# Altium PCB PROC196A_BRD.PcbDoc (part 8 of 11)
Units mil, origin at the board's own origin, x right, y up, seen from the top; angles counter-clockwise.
Board outline 3346.45 x 4921.26 mil, 8 copper layers (Top Layer, GND1, SIG1, PWR1, PWR2, SIG2, GND2, Bottom Layer), stack 54.534 mil thick; 736 components, 498 nets, 3030 pads, 1279 vias.
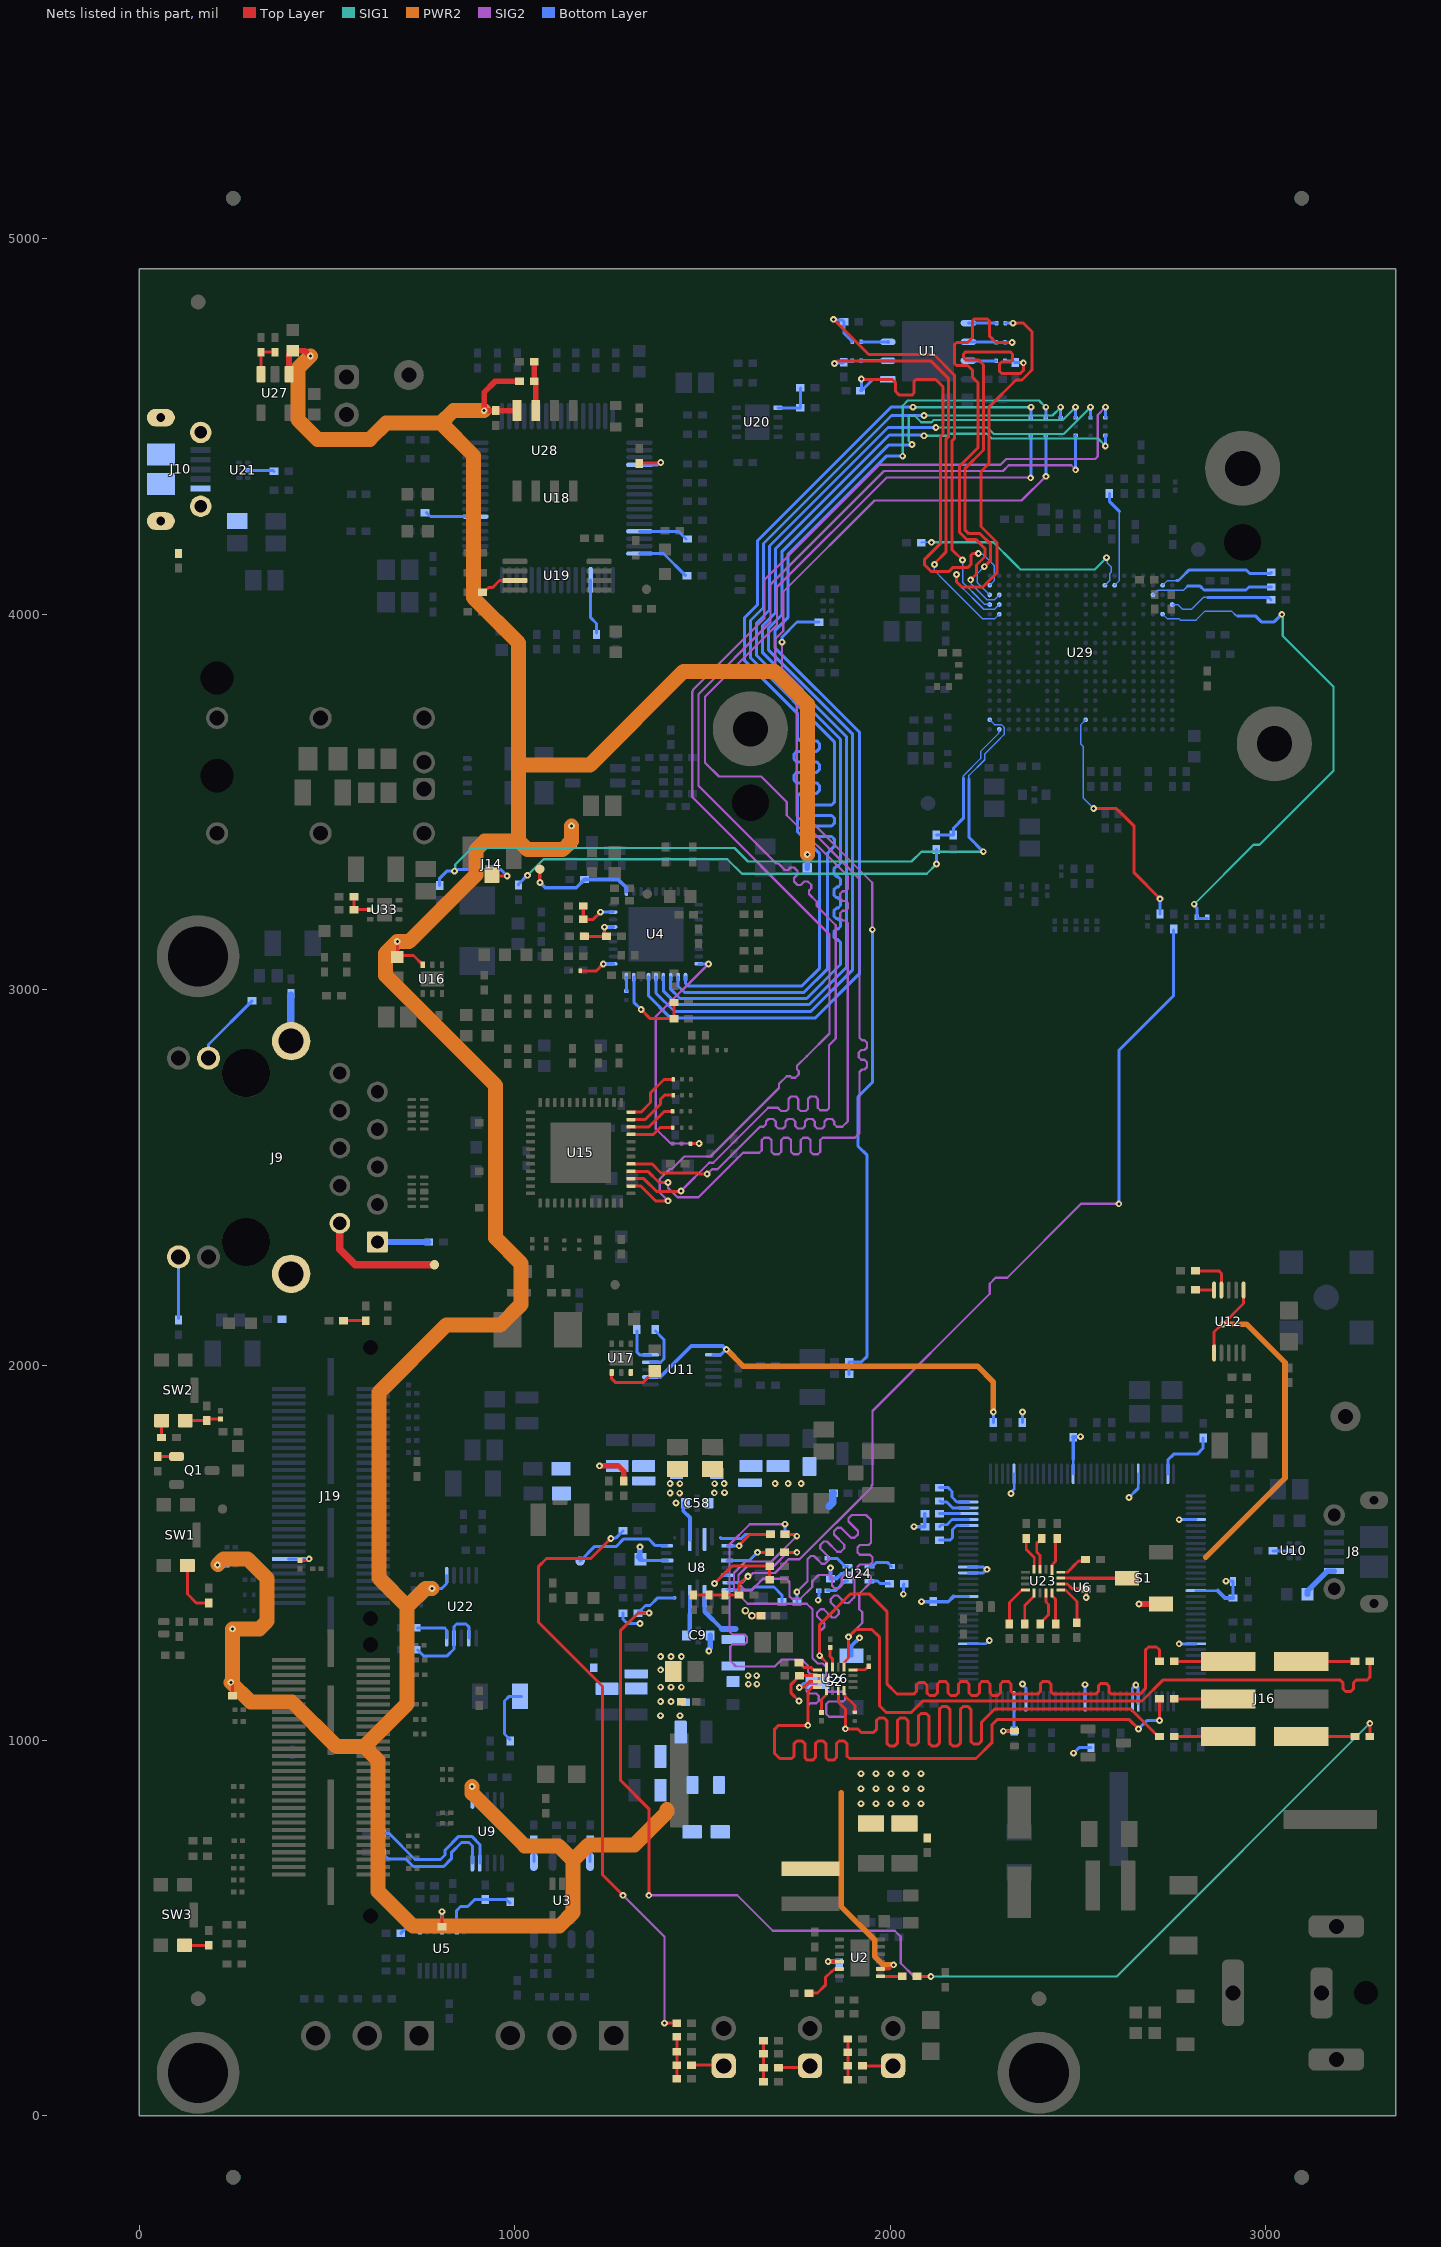
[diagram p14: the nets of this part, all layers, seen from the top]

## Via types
v1: diameter 18, hole 8, Top Layer to Bottom Layer, tented both sides, 1230 vias
v2: diameter 19.68, hole 7.87, Top Layer to Bottom Layer, 30 vias
v3: diameter 20, hole 10, Top Layer to Bottom Layer, tented both sides, 11 vias
v4: diameter 10, hole 4, SIG2 to Bottom Layer, tented both sides, 6 vias
v5: diameter 19.68, hole 7.87, Top Layer to Bottom Layer, tented both sides, 2 vias

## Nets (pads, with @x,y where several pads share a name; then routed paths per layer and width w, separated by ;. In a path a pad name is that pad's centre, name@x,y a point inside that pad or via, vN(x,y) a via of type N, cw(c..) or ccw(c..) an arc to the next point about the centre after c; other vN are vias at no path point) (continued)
NetJ8_5: J8.5 R175.2 | length 101.3
  Bottom Layer w15: R175.2@3112.06,1389.75 3112.06,1398.09 3165.02,1451.05 J8.5@3183.06,1451.05
NetJ9_1: J9.1 R400.1 | length 136.7
  Bottom Layer w15: J9.1@634.18,2327.93 R400.1@770.84,2327.93
NetJ9_2: J9.2 TP6.1 | length 338.4
  Top Layer w20: J9.2@534.18,2377.93 534.18,2308.46 575.32,2267.32 TP6.1@786.03,2267.32
NetJ9_11: J9.11 R69.1 | length 200.9
  Bottom Layer w8: J9.11@184.18,2817.7 184.18,2854.17 R69.1@300.41,2970.41
NetJ9_14: J9.14 R68.2 | length 164
  Bottom Layer w8: R68.2@104.25,2124.16 J9.14@104.25,2288.17
NetJ9_15: J9.15 R401.1
NetJ9_16: J9.16 R419.1 | length 122.8
  Bottom Layer w20: R419.1@403.86,2985.56 403.86,2863.36 J9.16@404.25,2862.97
NetJ10_1: J10.1 R206.1
NetJ10_6: J10.6 J10.7 J10.8 J10.9 J10.10 J10.11 R209.2
NetJ14_1: J14.1 R90.2 | length 95.6
  Top Layer w8: J14.1@939.4,3304.81 941.21,3303 v1(980,3303)
  Bottom Layer w8: R90.2@933.09,3320.81 962.19,3320.81 v1(980,3303)
NetJ16_1: J16.1 R5.2 | length 143.3
  Top Layer w8: R5.2@2757.14,1210.62 J16.1@2900.39,1210.62
NetJ16_2: J16.2 R61.1 | length 139.3
  Top Layer w8: J16.2@3095.27,1210.62 R61.1@3234.59,1210.62
NetJ16_3: J16.3 R167.2 | length 139.3
  Top Layer w8: R167.2@2761.07,1110.62 J16.3@2900.39,1110.62
NetJ16_5: J16.5 R176.2 | length 143.3
  Top Layer w8: R176.2@2757.14,1010.62 J16.5@2900.39,1010.62
NetJ17_1: J17.1 R300.2 | length 86.7
  Top Layer w8: R300.2@1471.02,135.11 1554.6,135.11 J17.1@1556.83,132.88
NetJ18_1: J18.1 R306.2 | length 84.4
  Top Layer w8: R306.2@1702.27,128.35 J18.1@1786.62,128.35
NetJ19_13: J19.13 R72.2 | length 89.4
  Top Layer w8: R72.2@427.98,1479.56 448.01,1479.56 v1(452.42,1483.98)
  Bottom Layer w8: J19.13@397.49,1483.81 456.43,1483.81 456.5,1483.88 452.52,1483.88 v1(452.42,1483.98)
NetJ20_1: J20.1 R311.2 | length 81.2
  Top Layer w8: R311.2@1926.71,133.08 J20.1@2007.9,133.08
NetL1_1: L1.1 U8.11 | length 142.1
  Bottom Layer w11: 1506,1342.9 U8.11@1506,1383.77
  Bottom Layer w12: 1506,1342.9 1552.01,1296.89
  Bottom Layer w15: 1552.01,1296.89 1588.19,1296.89
NetQ1_1: Q1.1 R266.2 | length 49.5
  Top Layer w8: R266.2@49.46,1756.63 Q1.1@99.01,1756.63
NetR1_1: R1.1 U2.5 | length 121.1
  Top Layer w8: R1.1@1783.91,326.87 1806.77,326.87 1827.57,347.67 1827.57,368.47 1842.33,383.23 ; 1843.25,384.15 1842.33,383.23 ; U2.5@1864.88,391.1 1852.05,391.1 1844.17,383.23 1842.33,383.23
NetR2_2: R2.2 U2.4 | length 56.9
  Top Layer w10: v1@1837.92,410.79 U2.4@1864.88,410.79
  Bottom Layer w10: v1(1834.92,410.78) R2.2@1855.07,410.78 ; R2.2@1855.08,410.79 R2.2@1864.88,410.79
NetR3_2: R3.2 U29.P20 | length 284.2
  Bottom Layer w4: U29.P20@2751.52,4026.2 2766.34,4026.2 2779.17,4013.37 2802.64,4013.37 2834.27,4045 2845.56,4045
  Bottom Layer w8: 2845.56,4045 3002.26,4045 3002.67,4044.59 3008.92,4044.59 R3.2@3014.76,4038.75
NetR4_2: R4.2 U2.7 | length 54
  Top Layer w8: U2.7@1974.33,371.42 R4.2@2028.34,371.42
NetR11_2: R11.2 U3.1 | length 58.1
  Bottom Layer w8: U3.1@1050.93,676.93 R11.2@1050.93,735.03
NetR12_2: R12.2 U3.4 | length 58.1
  Bottom Layer w8: U3.4@1200.93,676.93 R12.2@1200.93,735.03
NetR21_2: R21.2 U5.1 | length 58.1
  Bottom Layer w8: R21.2@696.51,486.19 714.23,503.91 U5.1@747.25,503.91
NetR25_2: R25.2 U5.4 | length 79.9
  Top Layer w8: R25.2@806.31,503.91 v1(806.31,543.87)
  Bottom Layer w8: U5.4@806.31,503.91 v1(806.31,543.87)
NetR27_1: R27.1 U9.5 | length 343.9
  Bottom Layer w8: R27.1@644.71,702.3 662.93,684.08 709.84,684.08 729.9,664.03 810.61,664.03 831.08,684.5 831.08,700.97 857.97,727.87 878.28,727.87 887.37,718.78 U9.5@887.37,673.26
NetR29_1: R29.1 U9.4 | length 382.7
  Bottom Layer w8: R29.1@644.71,752.49 664.91,752.49 734.59,682.81 802.15,682.81 814.2,694.86 814.2,707.57 851.1,744.47 885.41,744.47 907.05,722.82 U9.4@907.05,673.26
NetR31_2: R31.2 U29.T19 | length 312.1
  Bottom Layer w4: U29.T19@2725.93,4077.38 2738.65,4090.1 2746.2,4090.1 2746.24,4090.14 2756.81,4090.14 2756.84,4090.1 2763.44,4090.1
  Bottom Layer w8: 2763.44,4090.1 2768.33,4090.1 2777.67,4099.44 2797.04,4118.81 2925.19,4118.81 2948,4118.81 2958,4108.81 3012.48,4108.81 R31.2@3015.48,4111.81
NetR33_1: R33.1 U11.5 | length 95.3
  Bottom Layer w8: R33.1@1325.38,2090.69 1325.38,2052.36 1325.38,2034.89 1333.05,2027.22 U11.5@1361.7,2027.22
NetR35_1: R35.1 U11.4 | length 122.8
  Bottom Layer w8: U11.4@1361.7,2007.53 1388.65,2007.53 1390.85,2009.73 1397.04,2015.92 1397.04,2068.41 R35.1@1374.75,2090.69
NetR50_1: R50.1 R350.1 U4.8 | length 123
  Top Layer w8.3: R350.1@1182.57,3222.97 R50.1@1182.57,3187.4 1209.08,3187.4 v1(1228.3,3206.62)
  Bottom Layer w8: v1(1228.3,3206.62) U4.8@1262.03,3206.62
NetR53_2: R53.2 R54.2 U5.6 | length 201.8
  Bottom Layer w8: U5.6@845.68,503.91 845.21,504.38 845.21,547.17 855.58,557.53 874.69,557.53 893.01,575.85 R54.2@921.27,575.85 978.19,575.85 R53.2@987.76,566.27
NetR57_1: R57.1 U22.5 | length 101.5
  Bottom Layer w8: R57.1@741.42,1300.21 812.72,1300.21 818.5,1294.43 U22.5@818.5,1272.38
NetR58_1: R58.1 U12.5 | length 48.7
  Top Layer w8: R58.1@2813.85,2200.17 U12.5@2862.53,2200.17
NetR59_1: R59.1 U12.4 | length 116.4
  Top Layer w8: R59.1@2813.48,2251 2875.67,2251 2882.66,2244.01 U12.4@2882.66,2199.72
NetR62_1: R62.1 U22.2 U22.4 | length 245.8
  Bottom Layer w8: R62.1@741.42,1241.15 757.11,1225.47 819.92,1225.47 838.18,1243.72 U22.4@838.18,1272.38 838.18,1303.1 845.14,1310.06 870.2,1310.06 877.55,1302.71 U22.2@877.55,1272.38
NetR63_1: R63.1 U8.1 | length 137.8
  Bottom Layer w8: U8.1@1548.07,1539.66 1549.24,1538.49 1604.24,1538.49 1615,1549.25 R63.1@1680.91,1549.25
NetR74_2: R74.2 U4.28 | length 2871.7
  SIG1 w6: v1(2061.17,4551.81) v1(2375.05,4551.79)
  Bottom Layer w8: U4.28@1454.94,3033.39 1454.94,3016.44 1461.09,3010.3 1765.12,3010.3 1812.28,3057.46 1812.28,3362 1753.86,3420.42 1753.86,3497.5 1753.86,3516.21 1760.86,3523.21 1804.31,3523.21 1811.31,3530.21 1811.31,3544.21 1804.31,3551.21 1750.84,3551.21 1743.84,3558.21 1743.84,3572.21 1750.84,3579.21 1804.31,3579.21 1811.31,3586.21 1811.31,3600.21 1804.31,3607.21 1750.84,3607.21 1743.84,3614.21 1743.84,3628.21 1750.84,3635.21 1804.31,3635.21 1811.31,3642.21 1811.31,3656.21 1804.31,3663.21 1760.86,3663.21 1753.86,3670.21 1753.86,3674.21 1753.86,3735.09 1611.51,3877.44 1611.51,3990.39 1646.18,4025.06 1646.18,4195.41 2002.59,4551.81 2016.88,4551.81 v1(2061.17,4551.81) ; R74.2@2375.03,4523.93 v1(2375.05,4551.79)
NetR77_2: R77.2 R79.2 U4.35 | length 236.9
  Top Layer w8: v1@1338.51,2948.92 v1(1336.83,2947.25) 1361.27,2922.81 R79.2@1423.88,2922.81 R77.2@1423.88,2965.88
  Bottom Layer w8: U4.35@1317.15,3033.39 1317.15,2966.94 v1(1336.83,2947.25)
NetR89_1: R89.1 R93.2 U4.6 | length 109.4
  Top Layer w8: R89.1@1185.77,3142.2 R93.2@1244.83,3142.2 1244.75,3142.2 1238.91,3148.05 v1(1238.91,3166.67)
  Bottom Layer w10: v1(1238.91,3166.67) 1239.42,3167.17 1261.95,3167.17 U4.6@1262.03,3167.25
NetR96_2: R96.2 U4.33 | length 2881.4
  SIG1 w6: v1(2033.5,4421.31) 2033.5,4556.01 2047.3,4569.81 2396.73,4569.81 v1(2414.74,4551.79)
  Bottom Layer w8: U4.33@1356.52,3033.39 1356.52,2983.68 1415.92,2924.28 1799.64,2924.28 1919.1,3043.74 1919.1,3685.11 1693.01,3911.2 1693.01,3956.63 1727.68,3991.3 1727.68,4159.57 1989.42,4421.31 v1(2033.5,4421.31) ; R96.2@2414.73,4523.93 v1(2414.74,4551.79)
NetR100_2: R100.2 U4.32 | length 2894.6
  SIG1 w6: v1(2058.5,4452.31) 2058.5,4452.94 2049.62,4461.83 2049.62,4525.49 2053.13,4529 2065.85,4529 2083.04,4511.81 2110.2,4511.81 2116.2,4517.81 2460.15,4517.81 v1(2494.13,4551.79)
  Bottom Layer w8: U4.32@1376.2,3033.39 1376.2,2990.9 1425.44,2941.66 1788.69,2941.66 1900.43,3053.4 1900.43,3680.72 1676.71,3904.44 1676.71,3963.38 1711.38,3998.05 1711.38,4166.99 1995.16,4450.77 2058.5,4450.77 v1(2058.5,4452.31) ; R100.2@2494.11,4523.93 v1(2494.13,4551.79)
NetR110_2: R110.2 SW3.2 | length 64.7
  Top Layer w8: SW3.2@120.14,454.37 R110.2@184.83,454.37
NetR117_1: R117.1 R120.1 | length 59.1
  Top Layer w8: R120.1@544.29,2118.25 R117.1@603.35,2118.25
NetR123_1: R123.1 U6.63 | length 100.8
  Bottom Layer w8: R123.1@2131.95,1673.35 2155.02,1673.35 2164.91,1663.45 2164.91,1648.5 2177.9,1635.51 U6.63@2208.34,1635.51
NetR124_1: R124.1 U6.61 | length 53
  Bottom Layer w8: R124.1@2131.95,1604.01 U6.61@2184.93,1604.01
NetR126_1: R126.1 U6.62 | length 83.5
  Bottom Layer w7.8: R126.1@2132.49,1638.28 2135.62,1635.15 2150.89,1635.15 2166.29,1619.76 U6.62@2208.34,1619.76
NetR127_1: R127.1 U6.60 | length 84.2
  Bottom Layer w7.8: R127.1@2131.95,1569.43 2137.17,1574.65 2151.28,1574.65 2164.9,1588.26 U6.60@2208.34,1588.26
NetR152_2: R152.2 U6.95 | length 171.1
  Bottom Layer w7.87: U6.95@2739.83,1710.31 2739.83,1747.02 2755.55,1762.73 2818.25,1762.73 2833.89,1778.37 R152.2@2833.89,1805.76
NetR156_1: R156.1 R172.2 R316.2 | length 2244.2
  SIG2 w6: v1(1712,3925.81) 1712,3854.87 1768.29,3798.58 1768.29,3469.52 1952.62,3285.19 v1(1952.62,3160)
  Bottom Layer w8: v1(1712,3925.81) 1712.18,3925.99 1712.18,3939.33 1752.25,3979.4 R316.2@1810.99,3979.4 ; R172.2@1891.09,1975.11 R156.1@1891.09,2008.78 1923.78,2008.78 1938.87,2023.87 1938.87,2558.78 1914.53,2583.12 1914.53,2714.6 1952.62,2752.69 v1(1952.62,3160)
NetR158_1: R158.1 U18.48 | length 147.7
  Bottom Layer w8: U18.48@1332.18,4162.05 1396.17,4162.05 R158.1@1455.36,4102.86
NetR159_2: R159.2 R409.1 U27.3 | length 93.2
  Top Layer w8: U27.3@323.96,4642.54 R159.2@323.96,4698.33 R409.1@361.36,4698.33
NetR162_1: R162.1 U18.52 | length 147.5
  Bottom Layer w8: U18.52@1202.25,4091.18 1202.25,3991.22 1217.86,3975.62 R162.1@1217.86,3950.19
NetR174_2: R174.2 U10.5 | length 43.8
  Bottom Layer w8: R174.2@3020.18,1505.18 U10.5@3064.01,1505.18
NetR178_2: R178.2 U4.31 | length 2851.2
  SIG1 w6: v1(2090.28,4475.81) 2154.9,4475.81 2160.09,4481 2258.37,4481 2271.11,4468.25 2554.06,4468.25 v1(2573.48,4448.83)
  Bottom Layer w8: U4.31@1395.89,3033.39 1395.89,2997.2 1432.68,2960.41 1784.39,2960.41 1884.13,3060.16 1884.13,3673.97 1660.41,3897.69 1660.41,3970.13 1695.08,4004.8 1695.08,4175.15 1998.04,4478.11 2087.98,4478.11 v1(2090.28,4475.81) ; v1(2573.48,4448.83) R178.2@2573.5,4476.69
NetR179_1: R179.1 U18.36 | length 119.1
  Top Layer w8: R179.1@1332.18,4398.27 1337.42,4403.51 1387.7,4403.51 v1(1389,4404.81)
  Bottom Layer w8: U18.36@1332.18,4398.27 1379.83,4398.27 1386.38,4404.81 v1(1389,4404.81)
NetR186_1: R186.1 U8.8 | length 174.8
  Bottom Layer w8: U8.8@1566.83,1400.69 1631.52,1400.69 1639.36,1408.53 1690.56,1408.53 1712.22,1386.87 R186.1@1712.22,1369.65
NetR188_1: R188.1 U26.8 | length 46.2
  Top Layer w7.5: U26.8@1901.26,1188.16 1933.54,1188.16 R188.1@1943.39,1198
NetR190_2: R190.2 R292.2 U8.4 | length 155.4
  Top Layer w8: v1(1646.48,1501.05) R190.2@1679.37,1501.05
  Bottom Layer w8: U8.4@1565.85,1479.43 1624.86,1479.43 v1(1646.48,1501.05) R292.2@1679.37,1501.05
NetR193_1: R193.1 U8.2 | length 128.3
  Top Layer w8: v1(1597.94,1518.5) 1597.94,1520.82 1626.37,1549.25 R193.1@1680.91,1549.25
  Bottom Layer w8: U8.2@1566.83,1518.8 1566.98,1518.65 1597.79,1518.65 v1(1597.94,1518.5)
NetR194_2: R194.2 U6.59 | length 106
  Bottom Layer w5.5: U6.59@2184.07,1572.51 U6.59@2208.34,1572.51
  Bottom Layer w8: R194.2@2131.36,1533.4 2159.56,1533.4 2166.24,1540.09 2166.24,1561.98 2176.78,1572.51 U6.59@2184.07,1572.51
NetR202_1: R202.1 R203.1 U20.5 | length 108.7
  Bottom Layer w8: U20.5@1701.01,4550.19 R203.1@1756.72,4550.19 ; R203.1@1760.66,4550.19 R202.1@1760.66,4603.23
NetR205_2: R205.2 U19.3 | length 99.1
  Top Layer w8: R205.2@914.04,4059.35 917.98,4059.35 929.81,4071.18 940.65,4071.18 959.53,4090.06 U19.3@1000.42,4090.06
NetR208_2: R208.2 U21.5 | length 71
  Bottom Layer w8: U21.5@288.63,4383.75 355.97,4383.75 R208.2@358.57,4381.16
NetR222_1: R222.1 U24.3 | length 56
  Bottom Layer w8: U24.3@1945.05,1424.16 1966.79,1424.16 1967.26,1423.7 1967.79,1423.7 1972.92,1418.57 1996.78,1418.57 R222.1@1998.19,1417.16
NetR223_1: R223.1 U26.11 | length 54.1
  Top Layer w8: R223.1@1840.23,1247.66 1840.23,1223.83 1846.14,1217.92 U26.11@1846.14,1196.03
NetR225_2: R225.2 U4.30 | length 2880.9
  SIG1 w6: v1(2121.66,4497.81) 2258.53,4497.81 2276.08,4480.25 2462.28,4480.25 v1(2533.82,4551.79)
  Bottom Layer w8: U4.30@1415.57,3033.39 1415.57,3001.35 1440.21,2976.71 1777.63,2976.71 1867.83,3066.91 1867.83,3067.51 1867.83,3126.21 1860.83,3133.21 1857.08,3133.21 1850.08,3140.21 1850.08,3154.21 1857.08,3161.21 1860.83,3161.21 1867.83,3168.21 1867.83,3182.21 1860.83,3189.21 1857.08,3189.21 1850.08,3196.21 1850.08,3210.21 1857.08,3217.21 1860.83,3217.21 1867.83,3224.21 1867.83,3238.21 1860.83,3245.21 1857.08,3245.21 1850.08,3252.21 1850.08,3266.21 1857.08,3273.21 1860.83,3273.21 1867.83,3280.21 1867.83,3294.21 1860.83,3301.21 1857.08,3301.21 1850.08,3308.21 1850.08,3322.21 1857.08,3329.21 1860.83,3329.21 1867.83,3336.21 1867.83,3368.21 1867.83,3667.22 1644.11,3890.94 1644.11,3976.88 1678.78,4011.55 1678.78,4181.9 1994.69,4497.81 v1(2121.66,4497.81) ; R225.2@2533.81,4523.93 v1(2533.82,4551.79)
NetR230_2: R230.2 U4.29 | length 2927
  SIG1 w6: v1(2090.5,4529.81) 2432.45,4529.81 v1(2454.44,4551.79)
  Bottom Layer w8: U4.29@1435.26,3033.39 1435.26,3010.08 1452.33,2993.01 1770.88,2993.01 1833.78,3055.91 1833.78,3364.25 1851.53,3382 1851.53,3401.2 1844.53,3408.2 1796.13,3408.2 1789.13,3415.2 1789.13,3429.2 1796.13,3436.2 1844.53,3436.2 1851.53,3443.2 1851.53,3457.2 1844.53,3464.2 1777.16,3464.2 1770.16,3471.2 1770.16,3485.2 1777.16,3492.2 1844.53,3492.2 1851.53,3499.2 1851.53,3531.2 1851.53,3660.47 1627.81,3884.19 1627.81,3983.63 1662.48,4018.3 1662.48,4188.65 2003.64,4529.81 v1(2090.5,4529.81) ; R230.2@2454.42,4523.93 v1(2454.44,4551.79)
NetR234_2: R234.2 U4.27 | length 678.5
  Top Layer w8: R234.2@1468.15,2590.02 v1@1491.44,2590.02
  SIG2 w6: v1(1491.5,2590.08) 1415.73,2590.08 1376,2629.81 1376,2928.44 v1(1516.38,3068.82)
  Bottom Layer w8: U4.27@1490.38,3068.82 v1(1516.38,3068.82)
NetR247_2: R247.2 U4.36 | length 37.1
  Bottom Layer w8: R247.2@1297.46,2996.34 U4.36@1297.46,3033.39
NetR249_2: R249.2 U4.1 | length 95.1
  Top Layer w8: R249.2@1174.57,3050.42 1217.62,3050.42 v1(1236.03,3068.82)
  Bottom Layer w10: v1(1236.03,3068.82) U4.1@1262.03,3068.82
NetR250_1: R250.1 R314.2 U33.2 | length 77.7
  Top Layer w8: R250.1@571.34,3247.26 R314.2@571.34,3213.22 U33.2@615.03,3213.22
NetR251_2: R251.2 TP3.1 U4.10 | length 300.2
  Top Layer w10: TP3.1@1066.56,3321.29 1066.56,3286.29 v1(1066.99,3285.86)
  Bottom Layer w10: v1(1066.99,3285.86) 1081.18,3271.66 1163.72,3271.66 R251.2@1185.77,3293.72 1275.41,3293.72 1297.46,3271.66 U4.10@1297.46,3261.74
NetR267_2: R267.2 SW1.2 | length 143.3
  Top Layer w8: SW1.2@127.97,1466.29 127.97,1390.03 151.71,1366.29 R267.2@185.16,1366.29
NetR283_1: R283.1 U26.13 | length 57.1
  Top Layer w8: R283.1@1757.43,1206.86 1770.47,1193.82 1789.94,1193.82 1795.6,1188.16 U26.13@1806.77,1188.16
NetR296_1: R296.1 U23.13 | length 112.4
  Top Layer w7.5: U23.13@2454.79,1400.84 2454.98,1400.66 2467.37,1400.66 2497.52,1370.5 R296.1@2497.52,1313.41
NetR298_1: R298.1 R299.2 R300.1 R302.2 | length 111.8
  Top Layer w8: R298.1@1431.65,98.61 R300.1@1431.65,135.11 R302.2@1431.65,171.07 R299.2@1431.65,210.44
NetR304_1: R304.1 R305.2 R306.1 R307.2 | length 109.6
  Top Layer w8: R304.1@1662.9,90.41 R306.1@1662.9,128.35 R307.2@1662.9,165.74 R305.2@1662.9,199.99
NetR308_1: R308.1 R310.2 R311.1 R313.2 | length 108.6
  Top Layer w8: R308.1@1887.34,96.1 R311.1@1887.34,133.08 R313.2@1887.34,169.19 R310.2@1887.34,204.71
NetR317_2: R317.2 U24.4 | length 64.8
  Bottom Layer w8: R317.2@1832.34,1399.06 1854.4,1399.06 1879.5,1424.16 U24.4@1886.78,1424.16
NetR318_2: R318.2 U24.1 | length 67.9
  Bottom Layer w8: U24.1@1945.05,1463.53 1952.7,1463.53 1963.84,1474.67 1992.57,1474.67 R318.2@2003.7,1463.53
NetR319_1: R319.1 U24.6 | length 61
  Bottom Layer w8: R319.1@1834.75,1485.22 1858.58,1485.22 1880.26,1463.53 U24.6@1886.78,1463.53
NetR333_1: R333.1 SW2.4 | length 44.9
  Top Layer w8: R333.1@59.15,1807.13 SW2.4@59.15,1852.07
NetR334_1: R334.1 R335.2 SW2.2 | length 95.6
  Top Layer w8: SW2.2@122.14,1852.07 R335.2@179.39,1852.07 183.74,1856.42 R334.1@215.95,1856.42
NetR353_2: R353.2 U23.16 | length 80.1
  Top Layer w7.5: U23.16@2454.79,1448.09 2472.15,1448.09 2486.55,1462.49
  Top Layer w8: 2486.55,1462.49 2502.09,1478.04 2516.94,1478.04 R353.2@2520.83,1481.93
NetR354_2: R354.2 U23.1 | length 84.4
  Top Layer w7.5: U23.1@2431.17,1453.99 2431.17,1467.77 2440.88,1477.49 R354.2@2440.88,1534.37
NetR355_2: R355.2 U23.3 | length 85.8
  Top Layer w7.5: U23.3@2399.67,1455.96 2399.67,1493.14 2390.76,1502.05 2390.76,1525.46 R355.2@2399.67,1534.37
NetR356_2: R356.2 U23.4 | length 91.1
  Top Layer w7.5: R356.2@2362.88,1538.3 2362.88,1508.43 2383.92,1487.39 U23.4@2383.92,1455.96
NetR357_2: R357.2 U23.9 | length 92.7
  Top Layer w7.5: R357.2@2358.88,1310.63 2358.88,1359.73 2383.92,1384.78 U23.9@2383.92,1392.97
NetR358_2: R358.2 U23.8 | length 112.9
  Top Layer w7.5: R358.2@2317.88,1310.63 2317.88,1367.17 2351.56,1400.84 U23.8@2360.3,1400.84
NetR359_2: R359.2 U23.12 | length 82.4
  Top Layer w7.5: U23.12@2431.17,1392.97 2431.17,1385.74 2440.88,1376.02 R359.2@2440.88,1314.57
NetR360_2: R360.2 U23.11 | length 94.2
  Top Layer w7.5: R360.2@2399.67,1310.63 2405.76,1316.72 2405.76,1318.69 2421.83,1334.76 2421.83,1362.19 2415.42,1368.6 U23.11@2415.42,1392.97
NetR377_2: R377.2 U26.4 | length 69.4
  Top Layer w7.5: U26.4@1877.64,1133.04 1877.64,1121.23 1906.18,1092.68 R377.2@1906.18,1075.51
NetR380_2: R380.2 U29.T14 | length 260.8
  Bottom Layer w4: U29.T14@2597.98,4077.38 2610.81,4090.21 2610.81,4274.54
  Bottom Layer w8: R380.2@2583.89,4321.73 2583.89,4301.46 2610.81,4274.54
NetR381_2: R381.2 U29.T13 | length 623.1
  SIG1 w6: v1(2110,4191.81) 2275,4191.81 2328.74,4138.07 2339.11,4127.7 2347,4119.81 2545.64,4119.81 2553.53,4127.7 2563.9,4138.07 v1(2576.83,4151)
  Bottom Layer w4: R381.2@2083,4190.81 2084,4191.81 v1(2110,4191.81) ; U29.T13@2572.39,4077.38 2585.15,4090.14 2585.15,4108.81 2589.68,4113.34 2589.68,4125.89 2587.87,4127.7 2578.21,4137.36 2578.21,4138.07 2578.21,4149.62 v1(2576.83,4151)
NetR386_2: R386.2 U29.B11 | length 645.5
  Top Layer w8: v1(2542.38,3483) 2602.77,3483 2625,3460.77 2650.13,3435.64 2650.13,3311.33 v1(2719.16,3242.3)
  Bottom Layer w4: U29.B11@2521.21,3719.11 2508.38,3706.29 2508.38,3661.87 2508.38,3658.75 2508.38,3654.02 2514.34,3648.06 2514.34,3511.04 v1(2542.38,3483)
  Bottom Layer w8: R386.2@2719.16,3201.57 v1(2719.16,3242.3)
NetR392_2: R392.2 U29.R18 | length 332.2
  Bottom Layer w4: U29.R18@2700.34,4051.79 2713.21,4064.66 2777.67,4064.66 2782.42,4064.66 2792.76,4075
  Bottom Layer w8: 2792.76,4075 2826.06,4075 2836.06,4065 2925.19,4065 2948.38,4065 2956.19,4072.81 R392.2@3015.58,4072.81
NetR399_1: R399.1 U26.1 | length 63.9
  Top Layer w7.5: R399.1@1817.43,1076.52 1817.43,1109.23 1830.39,1122.2 U26.1@1830.39,1135.01
NetR416_1: R416.1 R417.2 U28.7 | length 131.2
  Top Layer w15: R417.2@1051.89,4672.69 R416.1@1051.89,4620.96 1055.83,4617.02 U28.7@1055.83,4543.13
NetS1_2: S1.2 U23.15 | length 176.2
  Top Layer w8: U23.15@2454.79,1432.34 2484,1432.34
  Top Layer w10: 2484,1432.34 S1.2@2631.01,1432.34
NetS2_2: S2.2 U26.15 | length 110.6
  Top Layer w8.3: v1(1757.99,1140.91) 1759.85,1142.77 1770.82,1142.77 1784.72,1156.66 U26.15@1806.77,1156.66
  Bottom Layer w8: v1(1757.99,1140.91) 1768.9,1151.82 1801.93,1151.82 S2.2@1806.77,1156.66
NetTP8_1: TP8.1 U8.22 | length 263.1
  Bottom Layer w8: TP8.1@1174.27,1478.02 1213.48,1517.23 1270.88,1517.23 1290.67,1537.03 1356.39,1537.03 1374.61,1518.8 U8.22@1405.42,1518.8
NRST_FTDI: R166.1 U18.45 | length 132.8
  Bottom Layer w8: U18.45@1332.18,4221.1 1435.99,4221.1 R166.1@1456.49,4200.6
NRSTOUT: R99.2 R102.1 U8.6 | length 245.1
  Top Layer w8: v5(1532.2,1418.01) 1578.46,1464.28 R102.1@1679.37,1464.28 R99.2@1679.37,1428.39
  Bottom Layer w8: v5(1532.2,1418.01) 1542.89,1428.7 1542.89,1428.91 1554.04,1440.06 U8.6@1565.85,1440.06
OSC_CLK_OUT_ETH: R88.1 R259.1 | length 1208.3
  SIG1 w6: v1(1033.7,3304.81) 1076.7,3347.81 1566.2,3347.81 1605.2,3308.81 2078,3308.81 2097.44,3308.81 v1(2123.44,3334.81)
  Bottom Layer w8: R259.1@1010.04,3279.18 1010.04,3281.15 v1(1033.7,3304.81) ; R88.1@2123.18,3373.13 2123.18,3335.07 v1(2123.44,3334.81)
OSC_CLK_OUT_ETHERNET: R88.2 R95.2 U29.A2 | length 377.5
  Bottom Layer w4: 2194.95,3564.28 2194.95,3569.66 2240.9,3615.61 2240.9,3634.93 2290.1,3684.13 2290.1,3692.73 U29.A2@2290.89,3693.52
  Bottom Layer w8: R88.2@2123.18,3412.5 R95.2@2167.78,3412.5 2169.33,3412.5 2169.33,3430.96 2194.95,3456.58 2194.95,3564.28
OSC_CLKTOP: R90.1 R367.1 U29.B1 | length 2025.7
  SIG1 w6: v1(839.69,3315.81) 841.38,3317.5 841.38,3333.81 885.38,3377.81 1585.41,3377.81 1621.7,3341.51 2057.17,3341.51 2083.47,3367.81 v1(2248.33,3367.81)
  Bottom Layer w4: 2210,3561.58 2210,3570.81 2252.05,3612.86 2252.05,3627.84 2282.96,3658.75 2286.08,3661.87 2303.76,3679.55 2303.76,3699.13 2296.5,3706.39 2278.02,3706.39 U29.B1@2265.3,3719.11
  Bottom Layer w8: R367.1@800.05,3277.5 800.05,3297.11 818.69,3315.75 839.63,3315.75 v1(839.69,3315.81) 842.4,3315.81 847.4,3320.81 R90.1@893.72,3320.81 ; 2210,3561.58 2210,3406.14 v1(2248.33,3367.81)
PMIC_CLK: R75.1 R297.2 | length 1653.2
  Top Layer w8: v1(1256.04,1537.99) 1202.6,1484.55 1084.7,1484.55 1062.74,1462.6 1062.74,1315.42 1234.43,1143.73 1234.43,641.79 v1(1288.68,587.54) ; v1(1398.87,246.66) R297.2@1431.65,246.66
  SIG2 w6: v1(1288.68,587.54) 1398.87,477.35 v1(1398.87,246.66)
  Bottom Layer w8: v1(1256.04,1537.99) 1256.98,1538.94 1269.11,1538.94 R75.1@1288.39,1558.22
PMIC_CLK_OUT: R218.1 R220.1 U29.N19 | length 1414.8
  SIG1 w6: v1(2810.27,3228) 2968.42,3386.15 2984.07,3386.15 3181.25,3583.33 3181.25,3806.96 3045.76,3942.45 3045.76,3997.81 v1(3043.47,4000.1)
  Bottom Layer w4: U29.N19@2725.93,4000.61 2738.8,3987.74 2770.59,3987.74 2773.65,3984.68 2815.17,3984.68 2839.07,4008.58 2909.51,4008.58 2922.09,3996 2925.19,3996
  Bottom Layer w8: v1(2810.27,3228) 2810.27,3224.75 2817.15,3217.87 2817.15,3190.15 R220.1@2845,3190.15 ; 2925.19,3996 2973.12,3996 2989.12,3980 3023.36,3980 v1(3043.47,4000.1)
PMIC_EN: R4.1 R125.1 R185.2 U8.15 | length 3376.4
  Top Layer w8: v1(1357.25,587.54) 1357.25,818.34 1281.2,894.39 1281.2,1292.13 1328.28,1339.21 v1(1358.31,1339.21) ; R4.1@2075.59,371.42 v1@2107.41,371.42 ; R185.2@3277.9,1010.62 v1(3277.9,1045.76)
  SIG1 w6: v1@2107.41,371.42 v1(2108.41,371.42) 2603.56,371.42 v1(3277.9,1045.76)
  SIG2 w6: v1(1357.25,587.54) 1592.5,587.54 1687.04,493 2012.67,493 2028.66,477.01 2028.66,406.52 2063.76,371.42 v1(2108.41,371.42)
  Bottom Layer w8: v1(1358.31,1339.21) R125.1@1328.05,1339.21 1348.41,1359.56 1360.65,1359.56 1380.92,1379.84 U8.15@1425.9,1379.84
PMIC_NINT: R13.2 R17.2 R106.1 R210.1 R214.2 U8.7 | length 2565.7
  Top Layer w8: R210.1@1475.62,1387.47 R13.2@1517.62,1387.47 R17.2@1560.12,1387.47 R106.1@1597.79,1387.47 1597.79,1416.02 1618.77,1437 v5(1621.35,1437)
  SIG2 w6: v5(1621.35,1437) 1625.05,1437 1634.44,1446.39 1693.45,1446.39 1729.45,1482.39 1758.43,1482.39 1950.19,1674.15 1950.19,1679.21 1952.84,1681.86 1952.84,1877.76 2265.37,2190.29 2265.37,2216.9 2281.01,2232.54 2311.85,2232.54 2508.81,2429.49 v1(2609.22,2429.49)
  Bottom Layer w8: U8.7@1568.31,1420.38 1604.75,1420.4 v5(1621.35,1437) ; v1(2609.22,2429.49) 2609.22,2838.18 2755.57,2984.53 R214.2@2755.57,3159.44
PMIC_SPI_CLK: R63.2 R167.1 U26.16 | length 2766.4
  Top Layer w8: U26.16@1806.77,1140.91 1790.92,1140.91 1780.68,1130.67 v1(1780.68,1040.29) 1702.85,1040.29 1692.65,1030.09 1692.65,965.32 1697.99,959.98 1706.15,951.81 1737.65,951.81 1744.65,958.81 1744.65,991.42 1751.65,998.42 1765.65,998.42 1772.65,991.42 1772.65,954.28 1779.65,947.28 1793.65,947.28 1800.65,954.28 1800.65,991.42 1807.65,998.42 1821.65,998.42 1828.65,991.42 1828.65,954.28 1835.65,947.28 1849.65,947.28 1856.65,954.28 1856.65,991.42 1863.65,998.42 1877.65,998.42 1884.65,991.42 1884.65,958.81 1891.65,951.81 1923.65,951.81 2229,951.81 2271.04,993.85 2271.04,1041.38 2285.09,1055.42 2637.39,1055.42 v1(2662,1030.81) ; R167.1@2717.77,1110.62 2717.77,1053.04 v1(2718,1052.81)
  SIG2 w6: v1(1719.85,1576.1) 1626.29,1576.1 1571.93,1521.74 1571.93,1290.58 1574.03,1288.48 1580.53,1281.98 1612.08,1281.98 1618.58,1275.48 1618.58,1262.48 1612.08,1255.98 1580.53,1255.98 1574.03,1249.48 1574.03,1220.48 1574.03,1212.55 1589.77,1196.81 1693,1196.81 1711.84,1215.65 1764.14,1215.65 1780.98,1198.81 1780.98,1190.56 1780.98,1183.26 1787.48,1176.76 1803.61,1176.76 1810.11,1170.26 1810.11,1157.26 1803.61,1150.76 1784.07,1150.76 1777.57,1144.26 1777.57,1131.26 1784.07,1124.76 1803.61,1124.76 1810.11,1118.26 1810.11,1105.26 1803.61,1098.76 1787.48,1098.76 1780.98,1092.26 1780.98,1063.26 1780.98,1040.59 v1(1780.68,1040.29)
  Bottom Layer w8: v1(1719.85,1576.1) 1719.85,1549.68 R63.2@1720.28,1549.25 ; v1(2662,1030.81) 2684,1052.81 v1(2718,1052.81)
PMIC_SPI_CS0: R5.1 R190.1 U26.12 | length 2888.4
  Top Layer w8: R190.1@1718.74,1501.05 v1(1751.63,1501.05) ; U26.12@1830.39,1196.03 1830.39,1207.84 v1(1812.35,1225.88) 1812.35,1308.16 1894.67,1390.48 1944.65,1390.48 1992.33,1342.8 1992.33,1149.99 2018.32,1124 2038.37,1124 2038.95,1123.42 2059,1123.42 2063,1123.42 2070,1130.42 2070,1147.46 2077,1154.46 2091,1154.46 2098,1147.46 2098,1126.79 2105,1119.79 2119,1119.79 2126,1126.79 2126,1150.65 2133,1157.65 2147,1157.65 2154,1150.65 2154,1126.79 2161,1119.79 2175,1119.79 2182,1126.79 2182,1150.65 2189,1157.65 2203,1157.65 2210,1150.65 2210,1126.79 2217,1119.79 2231,1119.79 2238,1126.79 2238,1150.65 2245,1157.65 2259,1157.65 2266,1150.65 2266,1126.79 2273,1119.79 2287,1119.79 2294,1126.79 2294,1150.65 2301,1157.65 2315,1157.65 2322,1150.65 2322,1130.42 2329,1123.42 2337.97,1123.42 2389.31,1123.42 2393.31,1123.42 2400.31,1130.42 2400.31,1150.65 2407.31,1157.65 2421.31,1157.65 2428.31,1150.65 2428.31,1130.42 2435.31,1123.42 2447,1123.42 2543.61,1123.42 2547.61,1123.42 2554.61,1130.42 2554.61,1145.17 2561.61,1152.17 2575.61,1152.17 2582.61,1145.17 2582.61,1130.42 2589.61,1123.42 2607.54,1123.42 2665.61,1123.42 2680,1137.81 2680,1240.46 2688.64,1249.09 2710,1249.09 2717.77,1241.33 R5.1@2717.77,1210.62
  SIG2 w6: v1(1751.63,1501.05) 1726.95,1501.05 1690.7,1464.79 1619.92,1464.79 1595.93,1440.8 1595.93,1418.09 1613.73,1400.29 1630.87,1400.29 1661.55,1430.96 1723.03,1430.96 1732.05,1421.95 1732.05,1383.77 1738.5,1377.31 1760.5,1377.31 1792.27,1409.08 1792.27,1424.08 1809.05,1440.86 1827.2,1440.86 1838.48,1440.86 1844.98,1434.36 1844.98,1412.82 1851.48,1406.32 1864.48,1406.32 1870.98,1412.82 1870.98,1434.36 1877.48,1440.86 1880.48,1440.86 1892.95,1440.86 1904.94,1428.87 1904.94,1381.91 1898.04,1375.01 1889.28,1366.25 1880.08,1366.25 1860.3,1386.04 1851.1,1386.04 1841.91,1376.85 1841.91,1367.66 1863.4,1346.16 1863.4,1336.97 1854.21,1327.78 1845.02,1327.78 1823.53,1349.27 1814.33,1349.27 1805.14,1340.08 1805.14,1330.89 1824.93,1311.1 1824.93,1301.9 1822.81,1299.78 1812.35,1289.32 v1(1812.35,1225.88)
PMIC_SPI_MISO: R176.1 R193.2 U26.3 | length 2795.1
  Top Layer w8: R193.2@1720.28,1549.25 1746.63,1549.25 v1(1751.63,1544.25) ; U26.3@1861.89,1133.04 1861.89,1102.54 1880.79,1083.64 v1(1880.79,1031) 1913.23,1031 1922.43,1021.8 1952.16,1021.8 1956.16,1021.8 1963.16,1028.8 1963.16,1052.55 1970.16,1059.55 1984.16,1059.55 1991.16,1052.55 1991.16,992.57 1998.16,985.57 2012.16,985.57 2019.16,992.57 2019.16,1052.55 2026.16,1059.55 2040.16,1059.55 2047.16,1052.55 2047.16,994.81 2054.16,987.81 2068.16,987.81 2075.16,994.81 2075.16,1064.91 2082.16,1071.91 2096.16,1071.91 2103.16,1064.91 2103.16,992.57 2110.16,985.57 2124.16,985.57 2131.16,992.57 2131.16,1082.79 2138.16,1089.79 2152.16,1089.79 2159.16,1082.79 2159.16,992.57 2166.16,985.57 2180.16,985.57 2187.16,992.57 2187.16,1082.79 2194.16,1089.79 2208.16,1089.79 2215.16,1082.79 2215.16,997.66 2222.16,990.66 2236.16,990.66 2243.16,997.66 2243.16,1048.01 2251,1055.85 2278.75,1083.59 2641.36,1083.59 2708.5,1016.46 2711.92,1016.46 R176.1@2717.77,1010.62
  SIG2 w6: v1(1751.63,1544.25) 1684.17,1476.79 1614.94,1476.79 1583.93,1445.78 1583.93,1400.74 1620.44,1364.23 1777.96,1364.23 1792.98,1349.21 1792.98,1219.22 1807.39,1204.81 1820.44,1204.81 1830,1195.25 1830,1152.56 1830,1136 1836.5,1129.5 1874.11,1129.5 1880.61,1123 1880.61,1110 1874.11,1103.5 1836.5,1103.5 1830,1097 1830,1070.81 1832.81,1068 1838,1062.81 1877.28,1062.81 1880.79,1059.3 v1(1880.79,1031)
PMIC_SPI_MOSI: R61.2 R186.2 U26.9 | length 2860.4
  Top Layer w8: U26.9@1877.64,1196.03 1877.7,1196.09 1877.7,1207.91 1889.27,1219.48 v1(1889.27,1276.15) 1908.19,1295.07 1952.09,1295.07 1971.13,1276.02 1971.13,1092.91 1989.49,1074.55 2056.59,1074.55 2086.83,1104.79 2670.9,1104.79 2726.61,1160.51 3167.31,1160.51 3199.31,1160.51 3206.31,1153.51 3206.31,1137.46 3213.31,1130.46 3227.31,1130.46 3234.31,1137.46 3234.31,1153.51 3241.31,1160.51 3270.26,1160.51 3274.79,1165.04 3277.9,1168.15 R61.2@3277.9,1210.62
  SIG2 w6: v1(1751.63,1395.6) 1779.96,1423.93 1779.96,1467.65 1779.96,1482.77 1788.31,1491.12 1797.5,1491.12 1817.62,1471.01 1826.81,1471.01 1836,1480.2 1836,1489.39 1813.8,1511.6 1813.8,1520.79 1822.99,1529.98 1832.18,1529.98 1859.2,1502.96 1868.4,1502.96 1877.59,1512.15 1877.59,1521.34 1850.56,1548.37 1850.56,1557.56 1859.76,1566.75 1868.95,1566.75 1895.97,1539.73 1905.17,1539.73 1914.36,1548.92 1914.36,1558.11 1889.43,1583.04 1889.43,1592.24 1898,1600.81 1922.77,1600.81 1936,1600.81 1949,1587.81 1949,1555.98 1949,1526.97 1942.5,1520.47 1919.42,1520.47 1912.92,1513.97 1912.92,1500.97 1919.42,1494.47 1946.69,1494.47 1953.19,1487.97 1953.19,1474.97 1946.69,1468.47 1919.42,1468.47 1912.92,1461.97 1912.92,1448.97 1919.42,1442.47 1942.5,1442.47 1949,1435.97 1949,1432.96 1949,1421.81 1918,1390.81 1918,1349.81 1925.9,1341.91 1925.9,1312.78 v1(1889.27,1276.15)
  Bottom Layer w8: R186.2@1751.59,1369.65 v1(1751.63,1395.6) v1(1751.63,1395.6)
PMIC_WAKE: J16.6 R185.1 | length 143.3
  Top Layer w8: J16.6@3095.27,1010.62 3190.9,1010.62 R185.1@3238.53,1010.62
PMICOUT_1V0: C132.1 C134.1 L8.2 R71.2 R73.1 R111.1 | length 96.5
  Top Layer w15: v1(1225.73,1731.54) 1276.05,1731.54 1290.05,1717.54 R71.2@1290.05,1691.14
PMICOUT_1V2: C129.1 C130.1 L2.2 R30.1 R32.1 R291.2 | length 159.5
  Bottom Layer w8: R32.1@987.91,1002.01 972.72,1017.2 972.72,1105.08 985.26,1117.62 R30.1@1013.71,1117.62 R30.1@1017.64,1117.62
PMICOUT_1V8: C60.1 C125.1 C127.1 L9.2 R14.2 R104.1 U17.4 U17.6 | length 187.9
  Top Layer w8: U17.4@1258.35,1980.27 1258.35,1963.49 1267.68,1954.16 1342.71,1954.16 C60.1@1373.01,1984.46
  Bottom Layer w20: 1838.33,1624.25 1847.11,1633.02 1847.11,1658.8 1847.27,1658.96 R14.2@1848.92,1658.96
  other v1: 1694,1684.81 1728.5,1684.81 1763,1684.81
PVIN3V3: C3.2 C6.2 C7.1 C8.2 C9.1 C9.3 C15.1 C31.1 C58.1 C58.3 C143.1 C144.2 C153.2 C199.1 C200.1 C201.1 C202.1 L1.2 L10.2 R125.2 R200.2 U8.13 U8.20 U8.25 U8.27 | length 415.3
  Bottom Layer w8: R125.2@1288.68,1339.21 1288.68,1322.73 1299.59,1311.82 1331.21,1311.82 v1@1331.33,1311.7 ; C3.2@1333.97,1482.13 1336.66,1479.43 U8.20@1406.4,1479.43
  Bottom Layer w10: C58.3@1449.01,1632.06 1449.01,1611.48 1466.76,1593.73 1466.76,1534.7 U8.25@1466.56,1534.49 ; U8.13@1466.44,1383.96 1466.44,1336.17 1466.57,1336.04
  Bottom Layer w12: C9.3@1466.57,1288.65 1466.57,1336.04
  Bottom Layer w15: C3.2@1329.44,1488.91 C3.2@1335.09,1483.26 ; C3.2@1333.44,1488.91 v1(1333.44,1515.96) ; v1(1517.13,1238.33) 1517.13,1243.43 1520.52,1246.81 C9.1@1520.52,1279.6
  other v1: 1388.4,1065.8 1439.95,1065.8 1388.69,1103.8 1416.19,1103.8 1388.69,1141.8 1416.19,1141.8 1443.69,1141.8 1622.39,1149.79 1645,1149.79 1621.93,1172.41 1644.54,1172.41 1388.69,1188.16 1388.69,1223.96 1416.19,1223.96 1443.69,1223.96 1333.56,1311.7 1429.51,1632.56 1414.18,1658.91 1439.55,1658.79 1531.7,1659.78 1559.06,1659.9 1414.3,1684.28 1439.67,1684.16 1532.58,1684.16 1557.95,1684.28
QSPI_CS: R38.1 U1.1 U29.T1 | length 1199.6
  Top Layer w8: v1(1923.39,4627) 1924.58,4625.81 2005.86,4625.81 2014.85,4616.82 2014.85,4593.62 2024.47,4584 2057.94,4584 2063.86,4589.92 2063.86,4621.12 2068.55,4625.81 2121.42,4625.81 2141,4606.23 2141,4480.44 2134.59,4474.03 2134.59,4387.18 2134.59,4189.57 2092,4146.99 2092,4131.53 2108.72,4114.81 2157.33,4114.81 2166.85,4124.32 2206.73,4124.32 2215.14,4132.73 2215.14,4156.59 2220.55,4162 v1(2234.97,4162)
  Bottom Layer w4: v1(2234.97,4162) 2236.38,4160.59 2246.78,4160.59 2278.02,4129.35 2278.02,4108.29 2278.06,4108.26 2278.06,4097.69 2278.02,4097.65 2278.02,4090.1 U29.T1@2265.3,4077.38
  Bottom Layer w8: R38.1@1921.63,4595.86 1923.39,4597.62 v1(1923.39,4627) ; R38.1@1923.6,4595.86 1953.59,4625.85 U1.1@1993.92,4625.85
QSPI_D0: R45.2 U29.P2 | length 1125.3
  Top Layer w8: v1(2176.75,4106.32) 2176.75,4086.8 2190.55,4073 2217.96,4073 2218.62,4073 2247,4073 2284.81,4110.81 2284.81,4127.7 2284.81,4138.07 2284.81,4191.12 2242,4233.94 2242,4380.63 2248.56,4387.18 2264,4402.63 2264,4553.06 2335.26,4624.32 2351.35,4624.32 2366,4638.97 2365.76,4639.21 2378.61,4652.06 2378.61,4752.19 2355.24,4775.56 v1(2327.49,4775.56)
  Bottom Layer w4: v1(2176.75,4106.32) 2176.4,4105.97 2176.4,4086.49 2217.96,4044.93 2218.62,4044.27 2249.41,4013.48 2259.98,4013.48 2260.02,4013.44 2270.59,4013.44 2270.62,4013.48 2278.17,4013.48 U29.P2@2290.89,4026.2
  Bottom Layer w8: R45.2@2307.42,4775.85 2327.21,4775.85 v1(2327.49,4775.56)
QSPI_D0_FLASH: R45.1 U1.5 | length 74.9
  Bottom Layer w8: U1.5@2208.6,4775.85 R45.1@2283.51,4775.85
QSPI_D1: R39.1 R49.1 U29.N2 | length 1136.3
  Top Layer w8: v1(1851.8,4668) 1853.94,4668 1861.49,4675.55 2108.38,4675.55 2156,4627.93 2156,4474.23 2149.59,4467.82 2149.59,4387.18 2149.59,4166.87 2118.24,4135.52 v1(2118.24,4132.81)
  Bottom Layer w4: v1(2118.24,4132.81) 2118.24,4116.61 2145.71,4089.15 ; 2145.71,4089.1 2246.92,3987.89 2259.98,3987.89 2260.02,3987.85 2278.13,3987.85 U29.N2@2290.89,4000.61
  Bottom Layer w8: v1(1851.8,4668) 1853.63,4669.83 1874.43,4669.83 R49.1@1876.26,4671.66 1878.24,4673.64 1898.22,4673.64 1899.14,4674.56 R39.1@1899.14,4675.55
QSPI_D1_FLASH: R39.2 U1.2 | length 71.3
  Bottom Layer w8: R39.2@1922.76,4675.55 1922.91,4675.7 1993.77,4675.7 U1.2@1993.92,4675.85
QSPI_D2: R42.1 R43.1 U29.P1 | length 1139.6
  Top Layer w8: v1(1849.44,4786) 1943.44,4692 2116.87,4692 2171,4637.87 2171,4468.01 2164.59,4461.6 2164.59,4387.18 2164.59,4172.93 v1(2192.71,4144.81)
  Bottom Layer w4: v1(2192.71,4144.81) 2194.21,4143.31 2194.21,4084.37 2217.96,4060.62 2218.62,4059.96 2252.19,4026.39 2265.11,4026.39 U29.P1@2265.3,4026.2
  Bottom Layer w8: v1(1849.44,4786) 1851.35,4784.09 1872.46,4784.09 R43.1@1877.26,4779.29 1877.26,4748.71 1899.14,4726.83 R42.1@1899.14,4725.85
QSPI_D2_FLASH: R42.2 U1.3 | length 71.2
  Bottom Layer w8: R42.2@1922.76,4725.85 U1.3@1993.92,4725.85
QSPI_D3: R40.2 R41.1 U29.R1 | length 1128.5
  Top Layer w8: v1(2251.04,4127) 2267.97,4143.93 2267.97,4186.75 2239.76,4214.96 2209.62,4214.96 2199.24,4225.34 2199.24,4387.18 2199.24,4387.81 2249,4437.57 2249,4664.31 2235.09,4678.22 2201.4,4678.22 2195.45,4684.17 2195.45,4693.63 2200.14,4698.31 2321.32,4698.31 2326.01,4693.63 2326.01,4676.69 2321.32,4672 2296.65,4672 2291.96,4667.31 2291.96,4646.69 2296.65,4642 2347.33,4642 2354.83,4649.5 v1(2354.83,4670)
  Bottom Layer w4: v1(2251.04,4127) 2231.72,4107.68 2231.72,4085.37 U29.R1@2265.3,4051.79
  Bottom Layer w8: R40.2@2306.26,4675.15 2328.7,4675.15 R41.1@2333.26,4670.59 2333.55,4670.29 2354.54,4670.29 v1(2354.83,4670)
QSPI_D3_FLASH: R40.1 U1.7 | length 74.3
  Bottom Layer w8: U1.7@2208.6,4675.85 2209.24,4675.21 R40.1@2282.64,4675.21
QSPI_SCLK: R44.2 U29.R2 | length 1135.8
  Top Layer w8: v1(2214.72,4092) 2217.96,4095.24 2230.14,4107.42 2230.14,4131.56 2236.66,4138.07 2252.97,4154.39 2252.97,4174.88 2227.89,4199.96 2203.4,4199.96 2184.24,4219.13 2184.24,4387.18 2184.24,4394.03 2234,4443.79 2234,4617.22 2219.37,4631.85 2219.37,4650.63 2206.78,4663.22 2176.69,4663.22 2172,4667.91 2172,4719.31 2176.69,4724 2206.75,4724 2219.37,4736.62 2219.37,4782.31 2224.06,4787 2259,4787 2265.24,4780.76 2265.24,4740.76 2282,4724 v1(2325.22,4724)
  Bottom Layer w4: v1(2214.72,4092) 2216.4,4090.32 2216.4,4080.47 2217.96,4078.92 2218.62,4078.26 2257.85,4039.03 2270.59,4039.03 2270.62,4039.07 2278.17,4039.07 U29.R2@2290.89,4051.79
  Bottom Layer w8: R44.2@2306.26,4724.57 2306.55,4724.28 2324.94,4724.28 v1(2325.22,4724)
QSPI_SCLK_FLASH: R44.1 U1.6 | length 74.8
  Bottom Layer w8: U1.6@2208.6,4725.85 2281.72,4725.85 2282.64,4724.93 R44.1@2282.64,4724.57
REF_FTDI: R157.2 U18.6 | length 134.4
  Bottom Layer w8: R157.2@765.07,4270.79 775.38,4260.47 U18.6@895.17,4260.47
REGOUT_3V3: C18.2 C22.2 C23.1 C25.1 C26.1 C29.1 C41.1 C42.2 C43.2 C47.2 C48.1 C50.1 C61.1 C76.2 C98.2 C133.1 C145.1 FB1.1 L6.2 L10.1 R48.1 R124.2 R127.2 R134.2 R140.2 R155.2 R199.1 R200.1 R222.2 R243.2 R317.1 R416.2 R418.2 R503.1 R508.1 S1.1 S2.1 U2.8 U6.7 U6.8 U6.16 U6.26 U6.28 U6.39 U6.47 U6.51 U6.52 U6.69 U6.79 U6.90 U6.101 U6.113 U6.122 U9.6 U11.2 U11.6 U12.1 U12.6 U16.6 U22.6 U23.14 U24.5 U26.14 U27.1 U28.8 | length 14632.1
  Top Layer w8: v1(243.7,1154.99) 248.33,1150.35 R418.2@248.33,1119.56 ; C48.1@686.14,3090.45 C48.1@687.02,3091.34 ; v1@687.02,3126.76 C48.1@687.02,3091.34 ; U16.6@754.99,3066.73 730.38,3091.34 C48.1@687.02,3091.34 ; v1(1757.01,1105.38) 1736.41,1125.98 1736.41,1149.99 C18.2@1758.7,1172.28 1758.83,1172.41 U26.14@1806.77,1172.41 ; U2.8@1974.33,391.1 1998.67,391.1 v1(2009.68,402.12) ; v1(2301.76,1024.53) 2302.39,1025.16 v1@2307.39,1025.16 ; U23.14@2454.79,1416.59 2454.85,1416.53 2472.56,1416.53 2485.29,1403.8 2490.53,1403.8 ; U12.6@2862.98,2032.4 2862.98,2088.07 2883.96,2109.05 v1(2886.62,2109.05) 2941.72,2164.15 U12.1@2941.72,2199.72
  Top Layer w8.3: v1@2307.39,1025.16 C41.1@2330.38,1025.16
  Top Layer w10: 2490.53,1403.8 C98.2@2522.13,1403.8 C98.2@2522.43,1403.5 ; v1(2522.36,1380.82) 2522.25,1380.94 2522.25,1402.71 C98.2@2522.73,1403.19
  Top Layer w15: U27.1@398.76,4642.54 398.76,4692.58 C145.1@408.44,4702.26 441.45,4702.26 v1(455.38,4688.33) ; U28.8@1005.83,4543.13 1005.29,4542.59 C47.2@949.01,4542.59 v1(918.52,4542.59) 918.52,4591.26 948.21,4620.96 R416.2@1012.52,4620.96 ; v3(1632.08,1332.02) R199.1@1655.62,1332.02 ; v1(2663.06,1363.44) S1.1@2721.56,1363.44
  PWR2 w15: v1(1563.68,2042) 1608.47,1997.21 2232.52,1997.21 2274.9,1954.83 2274.9,1874.97 v1(2275.06,1874.81) ; 1869.59,860.89 1869.59,557.5 1959.07,468.01 1959.07,424.68 1981.63,402.12 v1(2009.68,402.12) ; 2840.72,1487.73 3052.13,1699.14 3052.13,2006.43 2949.52,2109.05 v1(2886.62,2109.05)
  PWR2 w40: v1@209.17,1469.15 220.73,1480.71 221.71,1480.71 224.49,1483.49 288.48,1483.49 340.62,1431.35 340.62,1317.89 320.09,1297.35 v1(248.33,1297.35) 248.33,1159.62 v1(243.7,1154.99) 295.79,1102.89 406.17,1102.89 525.26,983.8 599.52,983.8 ; v1(455.38,4688.33) 422,4654.95 422,4518.81 474.5,4466.31 614,4466.31 657.5,4509.81 803.56,4509.81 ; v1(779.8,1405.09) 762.12,1405.09 713.96,1356.93 713.1,1357.78 ; v1(886.65,877) 886.65,859.14 1026.54,719.24 1116.69,719.24 1155.34,680.59 ; v1(918.52,4542.59) 836.34,4542.59 803.56,4509.81 ; v1(1151.2,3436.52) 1151.2,3396.5 1127.77,3373.07 1033.85,3373.07 1010.42,3396.5 ; 1406,815.81 1406,808.93 1318.97,721.9 1196.65,721.9 1155.34,680.59 ; v1(1779.34,3360.51) 1779.34,3761.49 1692.64,3848.19 1449.81,3848.19 1200.27,3598.65 1010.42,3598.65 ; 599.52,983.8 635.85,947.47 635.85,598.13 728.87,505.11 1118.9,505.11 1155.34,541.55 1155.34,680.59 ; 599.52,983.8 713.1,1097.38 713.1,1357.78 ; 713.1,1357.78 638.29,1432.6 638.29,1927.22 817.82,2106.75 962.44,2106.75 1016.79,2161.1 1016.79,2270.87 948.66,2339 948.66,2745.33 655.59,3038.4 655.59,3096.83 v1(687.02,3128.26) 718.89,3128.26 896.63,3306.01 896.63,3373.07 920.06,3396.5 1010.42,3396.5 ; 803.56,4509.81 889.55,4423.82 889.55,4044.38 1010.42,3923.51 1010.42,3598.65 ; 1010.42,3396.5 1010.42,3598.65
  Bottom Layer w6: 2661.09,1671.64 U6.90@2661.09,1710.31
  Bottom Layer w7: U6.39@2208.34,1257.55 2254.76,1257.55 2263.76,1266.55 v1(2264.36,1266.55) ; v1(2321.76,1657.88) 2321.76,1660.86 2330.38,1669.48 U6.69@2330.38,1710.31 ; U6.79@2487.86,1710.31 2487.86,1750.1 ; U6.16@2519.36,1104.01 v1@2519.36,1147.29 ; U6.8@2645.34,1104.01 2645.34,1138.58 ; U6.113@2814.64,1399.28 2872.12,1399.28
  Bottom Layer w7.8: 2168.96,1383.54 U6.47@2208.34,1383.54
  Bottom Layer w8: v1(779.8,1405.09) 805.82,1405.09 818.5,1417.76 U22.6@818.5,1439.7 ; U11.2@1361.7,1968.16 1387.64,1968.16 ; v1(1808.33,1373.61) 1810.3,1375.58 R317.1@1810.3,1399.06 ; v1(2035.08,1389.64) 2036.32,1390.88 2036.32,1415.92 R222.2@2037.56,1417.16 ; U6.51@2208.34,1446.53 2247.9,1446.53 v1@2257.18,1455.81 ; U6.52@2208.34,1462.28 2248.83,1462.28 2255.29,1455.81 v1@2257.18,1455.81 ; v1(2258,1455.81) v1@2257.18,1455.81 ; R134.2@2275.06,1847.1 v1(2275.06,1874.81) ; v1(2301.76,1024.53) 2302.07,1024.85 C76.2@2330.38,1024.85 U6.28@2330.38,1104.01 ; R155.2@2352.4,1847.1 v1(2352.4,1874.81) ; v1(2353,1150.65) 2353,1147.95 2361.82,1139.13 2361.82,1104.07 U6.26@2361.88,1104.01 ; v1(2488.42,966.1) 2502.99,980.68 R140.2@2535.11,980.68 ; v1(2636.53,1647.07) 2661.09,1671.64 ; 2645.34,1138.58 v1(2654.71,1147.95) 2661.09,1141.57 U6.7@2661.09,1104.01 U6.7@2661.09,1097.79 ; v1@2771.35,1257.55 U6.122@2814.64,1257.55 ; v1@2771.35,1588.26 U6.101@2814.64,1588.26 ; v1(2895.17,1424.36) 2912.84,1424.36 C61.1@2913.5,1423.7 C43.2@2913.5,1379.55
  Bottom Layer w10: v1(207.63,1467.61) R508.1@231.46,1467.61 ; v1(248.33,1297.35) R503.1@278.9,1297.35 ; R243.2@753.28,1405.09 v1(779.8,1405.09) ; 1387.64,1968.16 1470.48,2051 1553.82,2051 1562.82,2042 v1(1563.68,2042) 1548.98,2027.3 1529.1,2027.3 U11.6@1529.02,2027.22 ; v1(1841.01,1459.75) C133.1@1841.01,1431.2 1857.45,1431.2 1870.1,1443.85 U24.5@1886.78,1443.85 ; S2.1@1897.32,1225.56 1897.32,1252.01 v1(1918.6,1273.28) ; v1@2063.71,1569.22 R127.2@2092.58,1569.43 R124.2@2092.58,1604.01 ; v1@2083.46,1369.65 2155.08,1369.65 2168.96,1383.54 ; C42.2@2487.6,1807.73 2488.41,1808.54 2506.47,1808.54 v1(2507.28,1809.35) ; 2487.86,1750.1 C42.2@2487.86,1807.46 ; 2872.57,1399.28 2892.3,1379.55 C43.2@2913.5,1379.55
  Bottom Layer w12: v1(886.65,877) 887.37,876.28 U9.6@887.37,840.58
  Bottom Layer w15: R48.1@1150.67,3393.26 v1(1151.2,3436.52) ; FB1.1@1779.34,3323.23 v1(1779.34,3360.51)
  other v1: 1922.34,831.57 1962.34,831.57 2002.34,831.57 2042.34,831.57 2082.34,831.57 1922.34,871.57 1962.34,871.57 2002.34,871.57 2042.34,871.57 2082.34,871.57 1922.34,911.3 1962.34,911.3 2002.34,911.3 2042.34,911.3 2082.34,911.3 2519.36,1148.59 2770.05,1257.55 2083.43,1369.68 2063.34,1569.43 2770.05,1588.26
  other v3: 1614.63,1346
RGMII_RD0: R325.2 U15.33 | length 118.7
  Top Layer w8: U15.33@1309.79,2614.75 1369.49,2614.75 1387.55,2632.81 R325.2@1421.05,2632.81
RGMII_RD1: R336.2 U15.34 | length 127.9
  Top Layer w8: U15.34@1309.79,2634.44 1357.29,2634.46 1398.95,2676.12 R336.2@1420.49,2676.12
RGMII_RD2: R338.2 U15.35 | length 146.7
  Top Layer w8: U15.35@1309.79,2654.12 1309.83,2654.16 1347.67,2654.16 1388.57,2695.06 1388.57,2708.31 1399.15,2718.89 R338.2@1421.93,2718.89
RGMII_RD3: R339.2 U15.36 | length 163.6
  Top Layer w8: U15.36@1309.79,2673.81 1336.13,2673.81 1361.99,2699.67 1361.99,2725.3 1397.78,2761.09 R339.2@1422.2,2761.09
RGMII_TCLK: R98.2 U15.29 | length 3465.5
  Top Layer w8: U15.29@1309.79,2536.01 1365.42,2536.01 1389.42,2512.02 1487.85,2512.02 1490.9,2508.97 v1(1512.85,2508.97)
  SIG2 w6: v1(1512.85,2508.97) 1525.69,2521.81 1540.42,2521.81 1653.4,2634.79 1660,2634.79 1663,2634.79 1669.5,2641.29 1669.5,2648.83 1676,2655.33 1689,2655.33 1695.5,2648.83 1695.5,2636.71 1702,2630.21 1715,2630.21 1721.5,2636.71 1721.5,2648.83 1728,2655.33 1741,2655.33 1747.5,2648.83 1747.5,2636.71 1754,2630.21 1767,2630.21 1773.5,2636.71 1773.5,2648.83 1780,2655.33 1793,2655.33 1799.5,2648.83 1799.5,2636.71 1806,2630.21 1819,2630.21 1825.5,2636.71 1825.5,2648.83 1832,2655.33 1845,2655.33 1851.5,2648.83 1851.5,2641.29 1858,2634.79 1866.28,2634.79 1872.68,2634.79 1887,2649.11 1887,2660.8 1887,3101.81 1887,3174.81 1887,3177.81 1880.5,3184.31 1873.5,3184.31 1867,3190.81 1867,3203.81 1873.5,3210.31 1881.34,3210.31 1887.84,3216.81 1887.84,3229.81 1881.34,3236.31 1873.5,3236.31 1867,3242.81 1867,3255.81 1873.5,3262.31 1880.5,3262.31 1887,3268.81 1887,3290.81 1887,3302.73 1725,3464.73 1725,3499.81 1657,3567.81 1543.89,3567.81 1507.06,3604.64 1507.06,3780.68 1698.68,3972.3 1698.68,4072.75 1990.74,4364.81 2373.59,4364.81 v1(2374.57,4363.83)
  Bottom Layer w8: v1(2374.57,4363.83) 2375.02,4364.27 2375.02,4387.18 2375.02,4475.77 R98.2@2375.03,4476.69
RGMII_TD0: R103.2 U15.28 | length 3484.8
  Top Layer w8: U15.28@1309.79,2516.33 1354.28,2516.33 1384.34,2486.27 v1(1408.62,2486.27)
  SIG2 w6: v1(1408.62,2486.27) 1408.62,2471.7 1433.52,2446.81 1489.46,2446.81 1608.27,2565.62 1623,2565.62 1651.5,2565.62 1658,2572.12 1658,2599.41 1664.5,2605.91 1677.5,2605.91 1684,2599.41 1684,2568.29 1690.5,2561.79 1703.5,2561.79 1710,2568.29 1710,2599.41 1716.5,2605.91 1729.5,2605.91 1736,2599.41 1736,2568.29 1742.5,2561.79 1755.5,2561.79 1762,2568.29 1762,2599.41 1768.5,2605.91 1781.5,2605.91 1788,2599.41 1788,2568.29 1794.5,2561.79 1807.5,2561.79 1814,2568.29 1814,2599.41 1820.5,2605.91 1833.5,2605.91 1906.08,2605.91 1918.53,2618.36 1918.53,2751.81 1918.53,2780.81 1925.03,2787.31 1932.03,2787.31 1938.53,2793.81 1938.53,2806.81 1932.03,2813.31 1923.31,2813.31 1916.81,2819.81 1916.81,2832.81 1923.31,2839.31 1932.03,2839.31 1938.53,2845.81 1938.53,2858.81 1932.03,2865.31 1925.03,2865.31 1918.53,2871.81 1918.53,2887.2 1918.53,3295.23 1751.29,3462.47 1751.29,3782.52 1694.18,3839.63 1694.18,3934.18 1715.68,3955.68 1715.68,4060.49 1958.19,4303 2050,4303 2350.36,4303 v1(2415.08,4367.72)
  Bottom Layer w8: R103.2@2414.73,4476.69 2414.73,4475.9 2414.86,4475.77 2414.86,4387.18 2414.86,4367.94 v1(2415.08,4367.72)
RGMII_TD1: R105.2 U15.27 | length 3506.1
  Top Layer w8: U15.27@1309.79,2496.64 1343.98,2496.64 1378.1,2462.53 1441.72,2462.53 v1(1443,2463.81)
  SIG2 w6: v1(1443,2463.81) 1518,2538.81 1528.73,2538.81 1675.23,2685.31 1701.39,2685.31 1703.5,2683.2 1710,2676.7 1723,2676.7 1729.5,2683.2 1729.5,2708.94 1736,2715.44 1749,2715.44 1755.5,2708.94 1755.5,2683.2 1762,2676.7 1775,2676.7 1781.5,2683.2 1781.5,2708.94 1788,2715.44 1801,2715.44 1807.5,2708.94 1807.5,2685.31 1814,2678.81 1829.76,2678.81 1832,2678.81 1837.28,2684.09 1837.28,2852 1855.42,2870.14 1855.42,3171.84 1804.42,3222.84 1804.42,3234.39 1783.92,3254.89 1783.92,3264.09 1789.96,3270.13 1789.96,3279.32 1780.77,3288.52 1771.57,3288.52 1762.22,3279.16 1753.03,3279.16 1743.83,3288.35 1743.83,3297.54 1753.19,3306.9 1753.19,3316.09 1744,3325.29 1734.81,3325.29 1728.76,3319.24 1719.57,3319.24 1702.57,3336.24 1696.76,3336.24 1489.59,3543.41 1489.59,3787.25 1681.68,3979.34 1681.68,4079.79 1983.7,4381.81 2301,4381.81 2316.19,4397 2482.53,4397 v1(2494.59,4384.94)
  Bottom Layer w8: R105.2@2494.11,4476.69 2494.35,4476.45 2494.35,4387.18 2494.35,4385.18 v1(2494.59,4384.94)
RGMII_TD2: R121.2 U15.26 | length 3455.5
  Top Layer w8: U15.26@1309.79,2476.96 1335.86,2476.96 1375.06,2437.76 v1(1408.51,2437.76)
  SIG2 w6: v1(1408.51,2437.76) 1386.63,2459.63 1386.63,2495.46 1413.36,2522.19 1418.3,2522.19 1451.92,2555.81 1521.69,2555.81 1704.14,2738.26 1704.14,2749.17 1724.64,2769.68 1733.83,2769.68 1738.32,2765.2 1747.51,2765.2 1756.7,2774.39 1756.7,2783.58 1752.22,2788.07 1752.22,2797.26 1777.76,2822.8 1838.42,2883.46 1838.42,3147.38 1472.59,3513.21 1472.59,3794.29 1474.75,3796.45 1474.75,3799.02 1664.68,3988.95 1664.68,4091.73 1971.76,4398.81 2293.96,4398.81 2309.15,4414 2546.35,4414 2552.91,4420.56 2552.91,4531.19 v1(2573.52,4551.79)
  Bottom Layer w8: R121.2@2573.5,4523.93 v1(2573.52,4551.79)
